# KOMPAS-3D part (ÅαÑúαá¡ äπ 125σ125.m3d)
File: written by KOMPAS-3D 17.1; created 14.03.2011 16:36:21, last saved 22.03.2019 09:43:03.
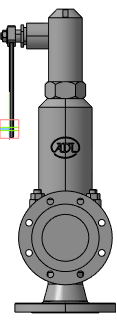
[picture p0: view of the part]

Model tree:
1. Плоскость XY
2. Плоскость ZX
3. Плоскость ZY
4. Ось X
5. Ось Y
6. Ось Z
7. Начало координат
8. Операция без истории:2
